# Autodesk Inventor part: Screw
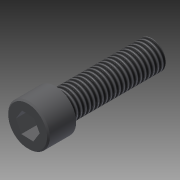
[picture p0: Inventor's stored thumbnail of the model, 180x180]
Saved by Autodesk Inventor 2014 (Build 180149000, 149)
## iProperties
Created: 2006-07
Part Number: Screw
Material: system_material_0
Description: SCREW, CAP, 1/4-20 X 3/8
Document SubType Name: Modeling
Designer: Z.MCGILL
Engineer: SAP
Manufacturer: Standard
Standards Organization: Custom
Mass: 26.2447 g
Surface Area: 18.9522 cm^2
Volume: 3.34682 cm^3
Density: 7.84168 g/cm^3
Appearance: system_RenderingStyle_0
NetWeight: 0.005
WeightUOM: KG
ModelCode: Comp
Author: Z.MCGILL
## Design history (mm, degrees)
node "SHCS"
body "Solid1"
tag "TaggingFeature2"
feature "DerivedBody::SHCS"
other parameters: "Thread_Length" = 44.45, "Head_Chamfer" = 0.635, "Thread_Chamfer" = 0.2286, "Thread_Diameter" = 12.7, "Head_Diameter" = 19.05, "Head_Length" = 12.7, "Hex_Head_Width" = 9.525, "Hex_Head_Depth" = 9.525, "d23" = 0, "d24" = 0
